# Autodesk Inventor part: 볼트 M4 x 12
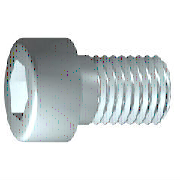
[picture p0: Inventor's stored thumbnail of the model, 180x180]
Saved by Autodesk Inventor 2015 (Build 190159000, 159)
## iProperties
IsCustomPart: 1
Created: 2012-02
Part Number: 볼트 M4 x 12
Material: 스테인리스강
Description: 6각 소켓 머리 캡 나사
Document SubType Name: Modeling
Standard: ISO 4762
Designer: mduedu
Standard Revision: Fourth edition 2004-03-01
Standards Organization: ISO
Language: ko-KR
Size Designation: M4 x 8
Categories: <MemberInstance><Categories><Category DisplayName="조임쇠" InternalName="e4da775c-781d-43d5-af7c-5136215cf5a6" Mnemonic="FSTN"><Category DisplayName="볼트" InternalN
Density: 7.75 g/cm^3
Appearance: 반광택
Author: mduedu
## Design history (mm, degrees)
sketch "스케치1"
  geometry: L1 (-1, 0)-(12, 0); L2 (12, 0)-(12, 2); L3 (12, 2)-(1.75, 2); L4 (1.75, 2)-(1.32, 2); L5 (1.32, 2)-(0, 2); L6 (0, 2)-(0, 3.5); L7 (0, 3.5)-(-4, 3.5); L8 (-4, 3.5)-(-4, 1.732); L9 (-4, 1.732)-(-2, 1.732); L10 (-2, 1.732)-(-1, 0); L11 (-7.2, 0)-(15.2, 0) reference; L12 (0, -0.7)-(0, 4.2) reference; L13 (1.75, 2)-(0, 2)
  constraints: 22 end point, 6 parallel, 2 collinear, 2 perpendicular, 1 horizontal, 1 point on line
  dimensions: "d1" = 10.25 distance from line of L3.end L2 (= GEL); "d2" = 0.42952 distance of L4.end L3.end (computed from GAL); "d3" = 4 distance between parallel lines of L8 L6 (= KOH); "d4" = 2 distance of L8.end L9.end (= INTI); "d5" = 60 deg angle of L10 L1; "d6" = 4 diameter of L3 L1 (= GD); "d7" = 4 diameter of L5 L1 (= BDM); "d8" = 3.4641 diameter of L9 L1 (= 1.1547 x SW); "d9" = 7 diameter of L7 L1 (= KOD); "d26" = 12 distance between parallel lines of L12 L2 (= NLG)
revolve "본체" sketch "스케치1" stored, may be unused: angle "d10" = 90 deg
sketch "스케치2"
  geometry: L1 (0, -4.9)-(0, 4.9) reference; L2 (-4.9, 0)-(4.9, 0) reference; L3 (1.732, 0)-(0.866, -1.5); L4 (0.866, -1.5)-(-0.866, -1.5); L5 (-0.866, -1.5)-(-1.732, 0); L6 (-1.732, 0)-(-0.866, 1.5); L7 (-0.866, 1.5)-(0.866, 1.5); L8 (0.866, 1.5)-(1.732, 0); 2 further points
  constraints: 12 end point, 1 coincident, 1 horizontal alignment, 1 point on line, 12 other
extrude "슬롯" join sketch "스케치2" stored distance "d11" = 10; taper "d12" = 0 deg
workplane "Work Plane1"
fillet "Fillet2" dims "d30" = 0.1 (= R)
body "Solid1"
fillet "모깎기1" dims "d17" = 0.4 (= RR)
feature "스레드" dims "d13" = 10.25 (= GEL), "d14" = 0
chamfer "모따기1" distance "d15" = 0.42941 (= -0.5 x SPD + 0.5 x GD); stored, may be unused: second distance "d16" = 0.42941 (= GUL), angle "d27" = 45 deg
other parameters: "GD" = 4 [user parameter; used in 2 equation terms], "NLG" = 12 [user parameter; used in 1 equation term], "GEL" = 10.25 [user parameter; used in 2 equation terms], "KOD" = 7 [user parameter; used in 1 equation term], "KOH" = 4 [user parameter; used in 1 equation term], "INTI" = 2 [user parameter; used in 1 equation term], "GAL" = 0.42941 (= 0.61345 x PTC) [user parameter; used in 1 equation term], "GUL" = 0.42941 (= 0.61345 x PTC) [user parameter; used in 1 equation term], "BDM" = 4 (= NND) [user parameter; used in 1 equation term], "SW" = 3 [user parameter; used in 2 equation terms], "RR" = 0.4 [user parameter; used in 1 equation term], "SPD" = 3.14117 (= NND - 1.2269 x PTC) [user parameter; used in 1 equation term], "d19" = 0, "d28" = 0, "d29" = 0, "R" = 0.1 [user parameter; used in 1 equation term], "TOA" = 30 deg [user parameter], "GD1" = 3.14117 (= THREADDIA - 1.2269 x PTC) [user parameter], "THREADDIA" = 4 [user parameter; used in 1 equation term], "FAWI" = 45 deg [user parameter], "TPU" = 14.28571 (computed from PTC) [user parameter], "PTC" = 0.7 [user parameter; used in 5 equation terms], "NND" = 4 [user parameter; used in 2 equation terms], "E0" = 3.465 (= 1.155 x SW) [user parameter]
